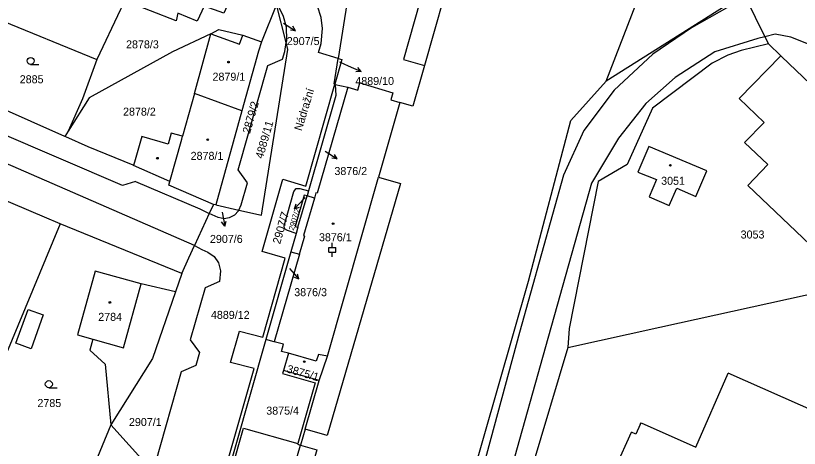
# Model space of a CAD drawing. Extents: x -527335 to -526256, y -1079142 to -1077836.
# Drawn here: x -526891.4 to -526725, y -1078806.1 to -1078714.2 of the extents above; entities that cross this region are included whole.
import ezdxf

# ---------------------------------------------------------------- set-up
doc = ezdxf.new("R2010")
doc.units = 0
for name, color, linetype in [('Hranice parcel', 7, 'Continuous'), ('Parcelní čísla', 7, 'Continuous'), ('Pop  PČ popisy', 7, 'Continuous'), ('Vnitřní kresba', 7, 'Continuous'), ('Značky budov', 7, 'Continuous'), ('Značky kultur', 7, 'Continuous')]:
    doc.layers.add(name, color=color, linetype=linetype)

msp = doc.modelspace()

# ---------------------------------------------------------------- linework, layer by layer
at = {"layer": 'Hranice parcel'}
for p, q in [((-526796.21, -1078695.13), (-526804.6, -1078724.76)), ((-526819.43, -1078701.36), (-526822.95, -1078723.3)), ((-526736.78, -1078709.62), (-526766.02, -1078728.13)), ((-526836.05, -1078711.79), (-526839.19, -1078719.76)), ((-526833.99, -1078719.88), (-526836.05, -1078711.79)), ((-526853.47, -1078730.76), (-526850, -1078718.03)), ((-526833.92, -1078719.44), (-526833.99, -1078719.88)), ((-526834.28, -1078721.82), (-526833.99, -1078719.88)), ((-526833.6, -1078721.4), (-526833.99, -1078719.88)), ((-526728.91, -1078722.73), (-526731.58, -1078720.17)), ((-526839.2, -1078756.6), (-526833.6, -1078721.4)), ((-526823.64, -1078728.74), (-526823.55, -1078728.79)), ((-526823.55, -1078728.79), (-526820.87, -1078729.39)), ((-526880.94, -1078739.86), (-526903.84, -1078729.73)), ((-526843.4, -1078734.39), (-526853.47, -1078730.76)), ((-526843.4, -1078734.39), (-526848.91, -1078754.35)), ((-526880.24, -1078738.74), (-526880.94, -1078739.86)), ((-526881.96, -1078758.41), (-526909.05, -1078746.98)), ((-526831.48, -1078759.12), (-526829.54, -1078752.49)), ((-526849.41, -1078754.29), (-526850.31, -1078756.25)), ((-526848.91, -1078754.35), (-526849.41, -1078754.29)), ((-526848.91, -1078754.35), (-526844.03, -1078755.48)), ((-526844.03, -1078755.48), (-526843.54, -1078754.36)), ((-526850.31, -1078756.25), (-526853.42, -1078763.04)), ((-526844.03, -1078755.48), (-526844.11, -1078755.67)), ((-526844.03, -1078755.48), (-526839.2, -1078756.6)), ((-526881.96, -1078758.41), (-526900.23, -1078802.31)), ((-526856.12, -1078768.95), (-526881.96, -1078758.41)), ((-526832.99, -1078764.38), (-526838.29, -1078782.98)), ((-526856.12, -1078768.95), (-526857.46, -1078772.84)), ((-526836.49, -1078783.47), (-526838.29, -1078782.98)), ((-526774.18, -1078784.68), (-526790.21, -1078838.32)), ((-526871.22, -1078801.11), (-526877.03, -1078815.27)), ((-526863.41, -1078809.75), (-526871.22, -1078801.11)), ((-526829.95, -1078802.05), (-526830.92, -1078805.41))]:
    msp.add_line(p, q, dxfattribs=at)
for points in [[(-526766.02, -1078728.13), (-526758.54, -1078708.63), (-526747.6, -1078675.03)], [(-526796.21, -1078695.13), (-526797.53, -1078694.71), (-526797.63, -1078695.06), (-526800.78, -1078694.21), (-526809.06, -1078723.54), (-526804.6, -1078724.76)], [(-526822.95, -1078723.3), (-526827.09, -1078722.05), (-526826.54, -1078720.12), (-526826.24, -1078716.92), (-526826.57, -1078714.61), (-526827.31, -1078712.18), (-526828.95, -1078709.32), (-526834.61, -1078701.38)], [(-526736.78, -1078709.62), (-526736.47, -1078710.26), (-526732.32, -1078718.67), (-526731.58, -1078720.17)], [(-526868.26, -1078711.02), (-526869.17, -1078712.87), (-526874.21, -1078723.48)], [(-526845.53, -1078709.84), (-526847.23, -1078713.67), (-526851.39, -1078712.19), (-526852.86, -1078715.34), (-526856.99, -1078713.69), (-526857.33, -1078715.27), (-526868.26, -1078711.02)], [(-526836.01, -1078711.53), (-526835.83, -1078711.79), (-526834.6, -1078714.3), (-526833.95, -1078716.6), (-526833.92, -1078719.44)], [(-526903.84, -1078729.73), (-526895.72, -1078714.74), (-526874.21, -1078723.48)], [(-526850, -1078718.03), (-526848.26, -1078717.14), (-526843.17, -1078718.33), (-526839.19, -1078719.76)], [(-526850, -1078718.03), (-526858.12, -1078721.85), (-526875.81, -1078731.66), (-526880.24, -1078738.74)], [(-526839.19, -1078719.76), (-526839.85, -1078721.74), (-526843.4, -1078734.39)], [(-526731.58, -1078720.17), (-526737.37, -1078721.57), (-526740.22, -1078722.56), (-526743.53, -1078724.3), (-526756.16, -1078733.81), (-526761.57, -1078745.82), (-526767.69, -1078749.42), (-526773.89, -1078780.67), (-526774.18, -1078784.68)], [(-526843.54, -1078754.36), (-526842.21, -1078749.69), (-526844.14, -1078746.97), (-526837.84, -1078724.77), (-526834.74, -1078723.42), (-526834.28, -1078721.82)], [(-526728.91, -1078722.73), (-526737.79, -1078731.81), (-526732.46, -1078736.86), (-526736.62, -1078741.14), (-526731.71, -1078745.82), (-526735.95, -1078750.27), (-526722.75, -1078762.81), (-526718.49, -1078758.42), (-526714.33, -1078754.04), (-526705.71, -1078744.91)], [(-526705.71, -1078744.91), (-526728.8, -1078722.84), (-526728.91, -1078722.73)], [(-526874.21, -1078723.48), (-526877.22, -1078731.87), (-526880.24, -1078738.74)], [(-526823.64, -1078728.74), (-526823.81, -1078728.65), (-526822.95, -1078723.3)], [(-526822.95, -1078723.3), (-526822.16, -1078723.54), (-526823.64, -1078728.74)], [(-526804.6, -1078724.76), (-526807.05, -1078733.43), (-526809.84, -1078732.63)], [(-526884.44, -1079141.53), (-526861.26, -1079084.28), (-526853.99, -1079074.79), (-526822.82, -1079003.24), (-526818.77, -1078991.73), (-526809.1, -1078957.32), (-526811.39, -1078950.51), (-526823.11, -1078928.49), (-526800.47, -1078837.81), (-526799.62, -1078833.84), (-526796.71, -1078822.54), (-526795.22, -1078815.04), (-526782.49, -1078770.61), (-526773.56, -1078736.49), (-526766.02, -1078728.13)], [(-526852.48, -1078831.96), (-526854.54, -1078831.4), (-526855.56, -1078830.87), (-526856.3, -1078830.07), (-526856.84, -1078829.04), (-526856.96, -1078827.42), (-526856.79, -1078826.7), (-526851.86, -1078828.1), (-526840.8, -1078789.17), (-526845.77, -1078787.84), (-526843.88, -1078781.19), (-526838.92, -1078782.52), (-526834.15, -1078765.67), (-526839.09, -1078764.32), (-526834.71, -1078748.94), (-526829.81, -1078750.39), (-526823.64, -1078728.74)], [(-526823.55, -1078728.79), (-526823.45, -1078731.12), (-526829.23, -1078751.41), (-526829.54, -1078752.49)], [(-526820.87, -1078729.39), (-526827.37, -1078751.92), (-526827.65, -1078751.83), (-526827.97, -1078752.94), (-526829.54, -1078752.49)], [(-526820.87, -1078729.39), (-526818.77, -1078730.01), (-526818.32, -1078728.49), (-526811.29, -1078730.56), (-526811.74, -1078732.07), (-526809.84, -1078732.63)], [(-526853.47, -1078730.76), (-526855.98, -1078739.8), (-526858.36, -1078739.18), (-526859.03, -1078741.48), (-526864.64, -1078739.88), (-526866.19, -1078745.33), (-526866.24, -1078745.51), (-526866.37, -1078745.99)], [(-526809.84, -1078732.63), (-526814.37, -1078748.5), (-526809.68, -1078749.84), (-526825.28, -1078803.4), (-526829.95, -1078802.05)], [(-526866.37, -1078745.99), (-526866.48, -1078745.94), (-526876, -1078742.04), (-526880.77, -1078739.94), (-526880.94, -1078739.86)], [(-526751, -1078750.87), (-526746.96, -1078752.64), (-526744.65, -1078747.16), (-526756.93, -1078741.98), (-526759.3, -1078747.43), (-526755.3, -1078749.01), (-526756.92, -1078752.7), (-526752.65, -1078754.52), (-526751, -1078750.87)], [(-526849.41, -1078754.29), (-526858.86, -1078750.18), (-526858.65, -1078749.42), (-526866.37, -1078745.99)], [(-526829.54, -1078752.49), (-526830.17, -1078752.32), (-526832.08, -1078758.95), (-526831.48, -1078759.12)], [(-526844.11, -1078755.67), (-526844.96, -1078756.57), (-526846.07, -1078757.15), (-526847.14, -1078757.33), (-526848.4, -1078757.1), (-526850.31, -1078756.25)], [(-526831.48, -1078759.12), (-526831.87, -1078760.46), (-526832.99, -1078764.38)], [(-526853.42, -1078763.04), (-526851.9, -1078763.85), (-526850.58, -1078764.43), (-526849.29, -1078765.38), (-526848.37, -1078766.67), (-526847.89, -1078768.42), (-526848.14, -1078770.69), (-526851.19, -1078772.01), (-526854.35, -1078783.07), (-526852.4, -1078785.74), (-526853.18, -1078788.48), (-526856.25, -1078789.82), (-526861.71, -1078809.08)], [(-526856.12, -1078768.95), (-526854.62, -1078765.66), (-526853.42, -1078763.04)], [(-526832.99, -1078764.38), (-526831.12, -1078764.89), (-526836.49, -1078783.47)], [(-526857.46, -1078772.84), (-526864.73, -1078771.19), (-526874.53, -1078768.46), (-526878.3, -1078782.01), (-526875.01, -1078782.94), (-526875.66, -1078785.24), (-526872.42, -1078788.23), (-526871.22, -1078801.11)], [(-526857.46, -1078772.84), (-526862.33, -1078786.99), (-526871.22, -1078801.11)], [(-526774.18, -1078784.68), (-526754.63, -1078780.37), (-526719.57, -1078772.65)], [(-526838.29, -1078782.98), (-526851.34, -1078828.74), (-526852.48, -1078831.96)], [(-526833.51, -1078785.92), (-526834.66, -1078785.6), (-526834.94, -1078785.52), (-526834.53, -1078783.94), (-526836.49, -1078783.47)], [(-526833.51, -1078785.92), (-526834.56, -1078789.57), (-526834.76, -1078790.21), (-526827.84, -1078792.21), (-526831.53, -1078805.04)], [(-526829.95, -1078802.05), (-526826.96, -1078791.72), (-526825.22, -1078786.49), (-526827.08, -1078786.14), (-526827.6, -1078787.59), (-526833.51, -1078785.92)], [(-526852.48, -1078831.96), (-526849.88, -1078832.66), (-526848.34, -1078832.64), (-526847.17, -1078832.15), (-526846.16, -1078831.02), (-526845.7, -1078829.8), (-526850.63, -1078828.45), (-526843.06, -1078801.82), (-526831.53, -1078805.04)], [(-526830.92, -1078805.41), (-526827.43, -1078806.4), (-526834.91, -1078832.86), (-526838.57, -1078831.82)], [(-526838.57, -1078831.82), (-526838.51, -1078831.59), (-526830.92, -1078805.41)], [(-526831.53, -1078805.04), (-526831.59, -1078805.23), (-526830.92, -1078805.41)]]:
    msp.add_lwpolyline(points, dxfattribs=at)
at = {"layer": 'Pop  PČ popisy'}
for p, q in [((-526834.51, -1078715.81), (-526831.96, -1078717.4)), ((-526831.96, -1078717.4), (-526833.08, -1078717.29)), ((-526831.96, -1078717.4), (-526832.55, -1078716.45)), ((-526822.67, -1078723.99), (-526820.78, -1078724.84)), ((-526820.78, -1078724.84), (-526818.04, -1078726.06)), ((-526818.04, -1078726.06), (-526819.16, -1078726.11)), ((-526818.04, -1078726.06), (-526818.75, -1078725.2)), ((-526825.68, -1078743.01), (-526823.14, -1078744.6)), ((-526823.14, -1078744.6), (-526824.25, -1078744.49)), ((-526823.14, -1078744.6), (-526823.72, -1078743.65)), ((-526829.97, -1078752.9), (-526830.12, -1078753.06)), ((-526830.12, -1078753.06), (-526832.17, -1078755.26)), ((-526832.17, -1078755.26), (-526831.85, -1078754.18)), ((-526847.53, -1078755.95), (-526847.01, -1078758.91)), ((-526832.17, -1078755.26), (-526831.12, -1078754.86)), ((-526847.01, -1078758.91), (-526846.69, -1078757.83)), ((-526847.01, -1078758.91), (-526847.68, -1078758.01)), ((-526833.27, -1078767.9), (-526831.3, -1078770.17)), ((-526831.3, -1078770.17), (-526831.58, -1078769.08)), ((-526831.3, -1078770.17), (-526832.34, -1078769.74))]:
    msp.add_line(p, q, dxfattribs=at)
at = {"layer": 'Vnitřní kresba'}
for p, q in [((-526738.29, -1078711.31), (-526747.88, -1078716.79)), ((-526747.88, -1078716.79), (-526756.12, -1078722.39)), ((-526850, -1078718.03), (-526843.87, -1078720.28)), ((-526843.87, -1078720.28), (-526843.17, -1078718.33)), ((-526733.79, -1078719.02), (-526742.97, -1078721.85)), ((-526732.32, -1078718.67), (-526733.79, -1078719.02)), ((-526730.13, -1078718.15), (-526732.32, -1078718.67)), ((-526726.79, -1078718.76), (-526730.13, -1078718.15)), ((-526723.03, -1078720.23), (-526726.79, -1078718.76)), ((-526756.12, -1078722.39), (-526764.31, -1078729.99)), ((-526742.97, -1078721.85), (-526751.34, -1078727.31)), ((-526751.34, -1078727.31), (-526757.6, -1078732.85)), ((-526764.31, -1078729.99), (-526770.73, -1078738.59)), ((-526757.6, -1078732.85), (-526763.39, -1078740.22)), ((-526868.74, -1078750.29), (-526906.55, -1078734.05)), ((-526770.73, -1078738.59), (-526775.09, -1078748.11)), ((-526858.65, -1078749.42), (-526856.15, -1078740.41)), ((-526856.15, -1078740.41), (-526855.98, -1078739.8)), ((-526763.39, -1078740.22), (-526769.14, -1078749.74)), ((-526901.75, -1078741.96), (-526853.5, -1078762.97)), ((-526865.98, -1078749.45), (-526868.74, -1078750.29)), ((-526865.98, -1078749.45), (-526852.34, -1078755.25)), ((-526825.22, -1078786.49), (-526814.37, -1078748.5)), ((-526775.09, -1078748.11), (-526784.46, -1078781.51)), ((-526832.35, -1078751.52), (-526831.87, -1078750.94)), ((-526831.87, -1078750.94), (-526831.1, -1078750.88)), ((-526831.1, -1078750.88), (-526829.23, -1078751.41)), ((-526769.14, -1078749.74), (-526778.89, -1078784.53)), ((-526834.43, -1078758.82), (-526832.35, -1078751.52)), ((-526827.97, -1078752.94), (-526830.27, -1078760.91)), ((-526852.34, -1078755.25), (-526850.31, -1078756.25)), ((-526834.3, -1078759.44), (-526834.43, -1078758.82)), ((-526833.67, -1078759.85), (-526834.3, -1078759.44)), ((-526831.87, -1078760.46), (-526833.67, -1078759.85)), ((-526831.12, -1078764.89), (-526829.99, -1078760.99)), ((-526830.27, -1078760.91), (-526829.99, -1078760.99)), ((-526853.42, -1078763.04), (-526853.5, -1078762.97)), ((-526868.54, -1078784.76), (-526864.73, -1078771.19)), ((-526891.36, -1078783.74), (-526888.74, -1078776.62)), ((-526888.74, -1078776.62), (-526885.57, -1078777.74)), ((-526885.57, -1078777.74), (-526888.09, -1078784.94)), ((-526784.46, -1078781.51), (-526793.55, -1078815.2)), ((-526888.09, -1078784.94), (-526891.36, -1078783.74)), ((-526875.01, -1078782.94), (-526868.54, -1078784.76)), ((-526778.89, -1078784.53), (-526788.56, -1078818.84)), ((-526826.96, -1078791.72), (-526834.56, -1078789.57)), ((-526747.01, -1078805.88), (-526740.14, -1078790.15)), ((-526719.94, -1078799.06), (-526740.14, -1078790.15)), ((-526758.79, -1078801.05), (-526759.7, -1078803.09)), ((-526758.79, -1078801.05), (-526758.62, -1078800.66)), ((-526758.62, -1078800.66), (-526747.01, -1078805.88)), ((-526771.41, -1078826.69), (-526760.66, -1078802.66)), ((-526759.7, -1078803.09), (-526760.66, -1078802.66))]:
    msp.add_line(p, q, dxfattribs=at)
at = {"layer": 'Značky budov'}
for centre in [(-526846.22, -1078724.06), (-526850.64, -1078740.54), (-526861.3, -1078744.47), (-526752.39, -1078745.98), (-526824, -1078758.37), (-526871.4, -1078775.12), (-526830.12, -1078787.68)]:
    msp.add_circle(centre, 0.175, dxfattribs=at)
at = {"layer": 'Značky kultur'}
for p, q in [((-526888.23, -1078724.56), (-526886.48, -1078724.56)), ((-526824.18, -1078763.43), (-526824.18, -1078762.43)), ((-526824.93, -1078763.43), (-526823.43, -1078763.43)), ((-526824.93, -1078764.43), (-526824.93, -1078763.43)), ((-526824.93, -1078764.43), (-526823.43, -1078764.43)), ((-526824.18, -1078765.43), (-526824.18, -1078764.43)), ((-526823.43, -1078764.43), (-526823.43, -1078763.43)), ((-526884.37, -1078793.22), (-526882.62, -1078793.22))]:
    msp.add_line(p, q, dxfattribs=at)
for centre in [(-526888.23, -1078723.81), (-526884.37, -1078792.47)]:
    msp.add_circle(centre, 0.75, dxfattribs=at)

# ---------------------------------------------------------------- texts
at = {"layer": 'Parcelní čísla'}
for s, p in [('2878/3', (-526867.97, -1078721.14)), ('2907/5', (-526833.84, -1078720.44)), ('2879/1', (-526849.61, -1078728.01)), ('2885', (-526890.55, -1078728.55)), ('4889/10', (-526819.29, -1078728.92)), ('2878/2', (-526868.61, -1078735.43)), ('2878/1', (-526854.26, -1078744.82)), ('3876/2', (-526823.73, -1078748.05)), ('3051', (-526754.35, -1078750.12)), ('2907/6', (-526850.16, -1078762.47)), ('3876/1', (-526827.01, -1078762.11)), ('3053', (-526737.47, -1078761.53)), ('3876/3', (-526832.26, -1078773.78)), ('2784', (-526873.88, -1078779.02)), ('4889/12', (-526849.95, -1078778.6)), ('2785', (-526886.79, -1078797.33)), ('3875/4', (-526838.2, -1078798.94)), ('2907/1', (-526867.36, -1078801.36))]:
    msp.add_text(s, height=1.7, dxfattribs=at).set_placement(p)
for s, height, rotation, p in [('2879/2', 1.7, 74, (-526841.67, -1078739.38)), ('4889/11', 1.7, 74, (-526838.93, -1078744.7)), ('2907/7', 1.7, 74, (-526835.26, -1078762.82)), ('2907/2', 1.139, 74, (-526832.38, -1078759.89)), ('3875/1', 1.7, 344, (-526833.98, -1078789.94))]:
    msp.add_text(s, height=height, rotation=rotation, dxfattribs=at).set_placement(p)
at = {"layer": 'Pop  PČ popisy'}
msp.add_text('Nádražní', height=1.7, rotation=73, dxfattribs=at).set_placement((-526830.69, -1078738.78))

doc.saveas('drawing.dxf')
